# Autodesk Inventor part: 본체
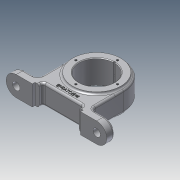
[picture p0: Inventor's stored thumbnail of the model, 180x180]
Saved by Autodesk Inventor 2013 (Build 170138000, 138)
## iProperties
Created: 2019-05
Part Number: 본체
Material: 알루미늄 6061
Document SubType Name: Modeling
Designer: a
Density: 2.71 g/cm^3
Mass: 457.66 g
Surface Area: 318.891 cm^2
Volume: 168.878 cm^3
Author: a
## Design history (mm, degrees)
sketch "스케치1"
  geometry: C1 r 40 at (0, 0); 1 further point
  constraints: 1 centre point, 1 coincident
  dimensions: "d0" = 80 diameter of C1
extrude "돌출1" new body sketch "스케치1" stored distance "d1" = 30; taper "d2" = 0 deg
sketch "스케치2"
  geometry: C1 r 40 at (0, 0) reference; C2 r 36 at (0, 0)
  constraints: 1 centre point, 1 coincident
  dimensions: "d3" = 72 diameter of C2
extrude "돌출2" join sketch "스케치2" distance "d4" = 3; taper "d5" = 0 deg
sketch "스케치3"
  geometry: C1 r 36 at (0, 0) reference; C2 r 26 at (0, 0)
  constraints: 1 centre point, 1 coincident
  dimensions: "d6" = 52 diameter of C2
extrude "돌출3" cut sketch "스케치3" stored distance "d7" = 3; taper "d8" = 0 deg
sketch "스케치4"
  geometry: L1 (0, 0)-(0, 31); C1 r 36 at (0, 0) reference; 1 further point
  constraints: 2 end point, 1 coincident, 1 vertical
  dimensions: "d9" = 31 distance of L1.start L1.end
hole "구멍1" sketch "스케치4" at (0, 31) diameter "d10" = 3.242; stored, may be unused: countersink angle "d14" = 90 deg, drill point angle "d16" = 118 deg; dims "d11" = 6, "d12" = 4, "d13" = 2, "d15" = 8
node "작업 평면1"
sketch "스케치5"
  geometry: 2 further points
  constraints: 1 coincident
hole "구멍2" sketch "스케치5" at (0, 0) diameter "d23" = 4.917; stored, may be unused: countersink angle "d27" = 90 deg, drill point angle "d29" = 118 deg; dims "d24" = 7, "d25" = 7, "d26" = 1, "d28" = 9
sketch "스케치6"
  geometry: C1 r 1 at (0, 0); 1 further point
  constraints: 1 centre point, 1 coincident
  dimensions: "d30" = 2 diameter of C1
extrude "돌출4" cut sketch "스케치6" stored distance "d31" = 3; taper "d32" = 0 deg
sketch "스케치7"
  geometry: L1 (2.458, 39)-(3.5, 39) reference; L2 (3.5, 39)-(3.5, 39.847) reference; L3 (-3.5, 39.847)-(-3.5, 39) reference; L4 (-3.5, 39)-(-2.458, 39) reference; L5 (-2.458, 39)-(-2.458, 30) reference; L6 (-2.458, 30)-(-1, 29.124) reference; L7 (-1, 29.124)-(-1, 25.981) reference; L8 (1, 25.981)-(1, 29.124) reference; L9 (1, 29.124)-(2.458, 30) reference; L10 (2.458, 30)-(2.458, 39) reference; L11 (-40, 0)-(-40, -60); L12 (-40, -60)-(40, -60); L13 (40, -60)-(40, 0); A1 r 40 centre (0, 0) between (-3.5, 39.847) and (3.5, 39.847) reference; A2 r 26 centre (0, 0) between (-1, 25.981) and (1, 25.981) reference; A3 r 40 centre (0, 0) between (-40, 0) and (40, 0); 1 further point
  constraints: 6 end point, 4 point on circle, 2 tangent, 1 centre point, 1 parallel, 1 perpendicular
  dimensions: "d33" = 60 distance of L11.start L11.end; "d34" = 80 distance of L11.end L12.end; "d35" = 60 distance of L12.end L13.end
extrude "돌출5" join sketch "스케치7" stored distance "d36" = 30; taper "d37" = 0 deg
sketch "스케치8"
  geometry: L1 (-40, -60)-(40, -60) reference; L2 (-36, -60)-(-36, -56); L3 (-36, -56)-(-30, -56); L4 (-30, -56)-(-30, -50); L5 (-30, -50)-(30, -50); L6 (30, -50)-(30, -56); L7 (30, -56)-(36, -56); L8 (36, -56)-(36, -60); L9 (-36, -60)-(36, -60); C1 r 36 at (0, 0) reference
  constraints: 16 end point, 4 perpendicular, 2 parallel, 2 point on line, 1 collinear
  dimensions: "d38" = 4 distance of L2.start L2.end; "d39" = 6 distance of L2.end L3.end; "d40" = 6 distance of L3.end L4.end; "d41" = 60 distance of L4.end L5.end; "d42" = 6 distance of L5.end L6.end; "d43" = 6 distance of L6.end L7.end; "d44" = 4 distance of L7.end L8.end; "d45" = 36 horizontal distance of L2.start C1.centre
extrude "돌출6" cut sketch "스케치8" stored distance "d46" = 30; taper "d47" = 0 deg
sketch "스케치9" dims "d50" = 30, "d51" = 30
  geometry: L1 (76, 30)-(76, 0) reference; L2 (80, 0)-(76, 0) reference; L3 (80, 0)-(80, 30) reference; L4 (76, 30)-(80, 30) reference; L5 (-20, 30)-(0, 30); L6 (0, 30)-(0, 0); L7 (0, 0)-(-20, 0); L8 (-20, 0)-(-20, 30); L9 (80, 30)-(100, 30); L10 (100, 30)-(100, 0); L11 (100, 0)-(80, 0); L12 (80, 0)-(80, 30); 5 further points
  constraints: 16 end point, 4 parallel, 2 coincident, 2 horizontal, 2 horizontal alignment, 2 perpendicular, 2 vertical alignment, 4 other
  dimensions: "d48" = 60 distance of point (-20, 15) point (40, 15); "d49" = 60 distance of point (100, 15) point (40, 15); "d52" = 30 distance of L9.end L10.end; "d53" = 30 distance of L7.end L5.start
extrude "돌출7" join sketch "스케치9" distance "d54" = 12; taper "d55" = 0 deg
sketch "스케치10"
  geometry: C1 r 9 at (-20, -15); C2 r 9 at (100, -15); A1 r 15 centre (-20, -15) between (-20, 0) and (-20, -30) reference; A2 r 15 centre (100, -15) between (100, -30) and (100, 0) reference; 1 further point
  constraints: 2 centre point, 2 coincident
  dimensions: "d56" = 18 diameter of C1; "d57" = 18 diameter of C2
extrude "돌출8" join sketch "스케치10" distance "d58" = 3; taper "d59" = 0 deg
sketch "스케치11"
  geometry: C1 r 9 at (0, 0) reference; C2 r 9 at (120, 0) reference; 3 further points
  constraints: 2 coincident
hole "구멍3" sketch "스케치11" at (0, 0), (120, 0) diameter "d60" = 11; stored, may be unused: countersink angle "d64" = 90 deg, drill point angle "d66" = 118 deg; dims "d61" = 8, "d62" = 4, "d63" = 2, "d65" = 10
fillet "모깎기3" dims "d67" = 6
chamfer "모따기1" distance "d70" = 1; stored, may be unused: second distance "d71" = 2, angle "d72" = 45 deg
fillet "모깎기6" dims "d73" = 3
fillet "모깎기7" dims "d74" = 3
sketch "스케치12"
  geometry: L1 (27, -47)-(-27, -47) reference; L2 (-27, -50)-(27, -50) reference; 2 further points
  constraints: 1 midpoint, 1 vertical alignment, 1 other
  dimensions: "d75" = 7 distance from line of L2 point (0, -43)
feature "엠보싱1" sketch "스케치12" dims "d76" = 0.5, "d77" = 0
sketch "스케치13"
  geometry: C1 r 1.5 at (0, 26); 1 further point
  constraints: 1 centre point, 1 vertical alignment, 1 other
  dimensions: "d78" = 3 diameter of C1
extrude "돌출9" cut sketch "스케치13" stored distance "d79" = 3; taper "d80" = 0 deg
fillet "모깎기8" dims "d81" = 3
fillet "모깎기9" dims "d82" = 3
node "솔리드1"
mirror "대칭1"
pattern_circular "원형 패턴1" dims angle "d18" = 360 deg
mirror "대칭2"
node "투영된 루프1"
node "절단 모서리 투영1"
